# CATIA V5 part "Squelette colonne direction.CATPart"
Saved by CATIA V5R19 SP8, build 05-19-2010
Part number: Squelette colonne direction
Publications: "Droite AB (colonne direction)", "Droite A (colonne direction)", "Droite B (colonne direction)", "Plan.2", "Plan.4", "Plan.8", "Plan.6"
Bounding box of the stored display mesh (mm): x 0 to 39, y 0 to 68, z -50 to 50
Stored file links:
  G:\EU_thinkMotion\CFAO_2010\MMS_groupe3\MMS_groupe3\A reprendre\lpastor\lpastor\Squelette colonne direction.CATPart
  C:\Users\Loïc\Documents\IFMA\Cours 2A\CFAO\Thinkmotion\Fourche avant.CATProduct
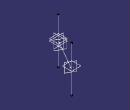
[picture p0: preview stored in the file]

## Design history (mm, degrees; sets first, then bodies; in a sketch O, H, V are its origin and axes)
Set1
  Point1 "A": linked copy from another document
  Point2 "B": linked copy from another document
Set2 "Set géométrique colonne direction"
  Line1 "Droite AB (colonne direction)": type PtPt, FirstPoint Point1, SecondPoint Point2
  Line2 "Droite A (colonne direction)": type PtDir, RefPoint Point1, Direction xy-plane, Start -50, End 50
  Line3 "Droite B (colonne direction)": type PtDir, RefPoint Point2, Direction xy-plane, Start -50, End 50
  Plane1: type Normal, Curve Line1, RefPoint Point1
  Plane2: type Offset, RefPlane Plane1, Offset 6
  Plane3: type Normal, Curve Line1, RefPoint Point2
  Plane4: type Offset, RefPlane Plane3, Offset 10, reversed
  Plane5: type Normal, Curve Line2, RefPoint Point1
  Plane6: type Offset, RefPlane Plane5, Offset 6
  Plane7: type Normal, Curve Line3, RefPoint Point2
  Plane8: type Offset, RefPlane Plane7, Offset 4
Body1 (main body)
